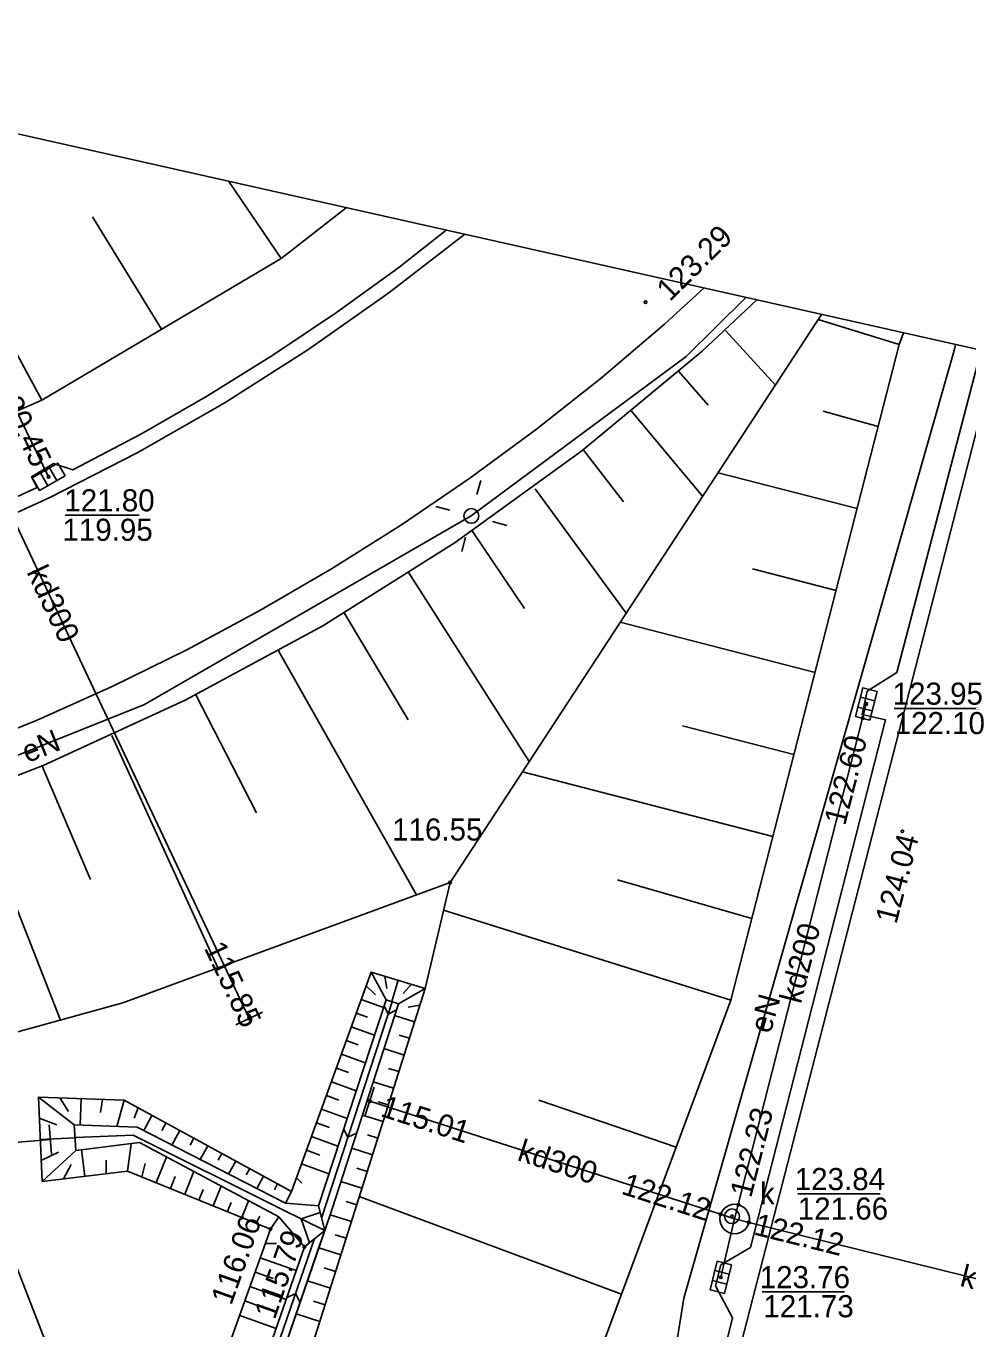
# Model space of a CAD drawing. Extents: x 6424617 to 6425697, y 5665845 to 5667190.
# Drawn here: x 6425429.62 to 6425461.6, y 5666996.15 to 5667040.37 of the extents above; entities that cross this region are included whole.
import ezdxf

# ---------------------------------------------------------------- set-up
doc = ezdxf.new("R2010")
doc.units = 0
for name, color, linetype in [('Warstwa 12', 7, 'Continuous'), ('Warstwa 13', 7, 'Continuous'), ('Warstwa 14', 7, 'Continuous'), ('Warstwa 15', 7, 'Continuous'), ('Warstwa 16', 7, 'Continuous'), ('Warstwa 2', 7, 'Continuous'), ('Warstwa 20', 7, 'Continuous'), ('Warstwa 21', 7, 'Continuous'), ('Warstwa 25', 7, 'Continuous'), ('Warstwa 4', 7, 'Continuous'), ('Warstwa 47', 7, 'Continuous'), ('Warstwa 5', 7, 'Continuous'), ('Warstwa 6', 7, 'Continuous'), ('Warstwa 63', 7, 'Continuous'), ('Warstwa 8', 7, 'Continuous'), ('Warstwa 9', 7, 'Continuous')]:
    doc.layers.add(name, color=color, linetype=linetype)

msp = doc.modelspace()

# ---------------------------------------------------------------- linework, layer by layer
at = {"layer": 'Warstwa 12'}
for points in [[(6425434.76, 5666984.14), (6425434.58, 5666984.61), (6425427.89, 5667001.89), (6425427.65, 5667002.33), (6425427.51, 5667002.81), (6425413.04, 5667037.72)], [(6425425.86, 5667034.37), (6425430.39, 5667025.07)], [(6425437.2, 5667006.68), (6425424.66, 5667033.24)], [(6425454.057, 5667031.16), (6425452.03, 5667029.15), (6425444.74, 5667023.74), (6425433.64, 5667017.34), (6425423.4, 5667013.24), (6425414.37, 5667010.94), (6425408.28, 5667009.82), (6425399.47, 5667009.19), (6425388.9, 5667009.91), (6425381.54, 5667011.18), (6425374.67, 5667013.05), (6425369.27, 5667014.85), (6425364.06, 5667017.3), (6425363.59, 5667017.98), (6425362.65, 5667017.64), (6425356.37, 5667020.95), (6425351.08, 5667024.44)], [(6425431.89, 5666906.96), (6425430.9, 5666907.63), (6425434.54, 5666922.46), (6425436.49, 5666936.39), (6425438.5, 5666937.81), (6425438.62, 5666938.07), (6425450.24, 5666986.45), (6425451.95, 5666997.19), (6425461.13, 5667029.36), (6425461.175, 5667029.564)], [(6425453.68, 5666999.88), (6425458.15, 5667017.36)], [(6425453.68, 5666999.88), (6425453.2, 5667000.04), (6425441.29, 5667003.88)], [(6425427.65, 5667002.33), (6425428.15, 5667002.38), (6425430.45, 5667002.58)], [(6425453.68, 5666999.88), (6425453.21, 5666997.9)], [(6425471.281, 5666995.531), (6425470.8, 5666995.65), (6425454.16, 5666999.76), (6425453.68, 5666999.88)]]:
    msp.add_lwpolyline(points, dxfattribs=at)
at = {"layer": 'Warstwa 14'}
for p, q in [((6425433.461, 5667023.772), (6425430.954, 5667023.772)), ((6425461.961, 5667017.21), (6425459.095, 5667017.21)), ((6425458.619, 5667000.732), (6425455.82, 5667000.732)), ((6425457.405, 5666997.405), (6425454.612, 5666997.405))]:
    msp.add_line(p, q, dxfattribs=at)
for centre in [(6425430.28, 5667025.295), (6425430.39, 5667025.07), (6425458.15, 5667017.36), (6425458.026, 5667016.876), (6425437.2, 5667006.68), (6425441.29, 5667003.88), (6425453.804, 5667000.364), (6425453.2, 5667000.04), (6425453.59, 5666999.97), (6425454.16, 5666999.76), (6425453.21, 5666997.9)]:
    msp.add_circle(centre, 0.045, dxfattribs=at)
at = {"layer": 'Warstwa 16'}
msp.add_circle((6425453.68, 5666999.88), 0.5, dxfattribs=at)
at = {"layer": 'Warstwa 2'}
msp.add_circle((6425444.74, 5667023.74), 0.25, dxfattribs=at)
at = {"layer": 'Warstwa 20'}
for points in [[(6425399.589, 5667018.967), (6425400.677, 5667019.039), (6425401.765, 5667019.127), (6425401.765, 5667019.127), (6425414.98, 5667022.07), (6425422.86, 5667024.48), (6425430.16, 5667027.67), (6425438.29, 5667032.48), (6425440.494, 5667034.201)], [(6425454.431, 5667031.077), (6425452.583, 5667029.336), (6425448.492, 5667025.953), (6425444.19, 5667022.842), (6425439.695, 5667020.016), (6425435.027, 5667017.487), (6425430.205, 5667015.265), (6425425.249, 5667013.361), (6425421.004, 5667012.016), (6425416.691, 5667010.907), (6425412.324, 5667010.035), (6425407.916, 5667009.405), (6425403.48, 5667009.017), (6425399.029, 5667008.872)], [(6425459.415, 5667029.959), (6425459.27, 5667029.56), (6425453.55, 5667007.3), (6425446.123, 5666987.348)], [(6425430.17, 5667001.148), (6425430.041, 5667004.011), (6425432.951, 5667003.909), (6425438.637, 5667000.815), (6425441.342, 5667008.258), (6425443.172, 5667007.705)], [(6425430.17, 5667001.148), (6425433.067, 5667001.506), (6425437.923, 5666999.537), (6425435.131, 5666991.725), (6425437.81, 5666990.75), (6425443.172, 5667007.705)]]:
    msp.add_lwpolyline(points, dxfattribs=at)
at = {"layer": 'Warstwa 21'}
for p, q in [((6425437.653, 5667006.893), (6425436.747, 5667006.467)), ((6425441.443, 5667004.356), (6425441.137, 5667003.404)), ((6425430.493, 5667002.082), (6425430.407, 5667003.078))]:
    msp.add_line(p, q, dxfattribs=at)
for points in [[(6425359.584, 5667018.749), (6425369.708, 5667010.452), (6425371.48, 5667010.531), (6425382.966, 5667006.762), (6425395.305, 5667004.278), (6425404.383, 5667003.424), (6425415.142, 5667003.76), (6425424.988, 5667005.033), (6425432.91, 5667007.21), (6425444.018, 5667011.301), (6425456.633, 5667030.583)], [(6425445.73, 5666975.503), (6425444.579, 5666975.856), (6425443.473, 5666976.33), (6425442.424, 5666976.919), (6425441.443, 5666977.617), (6425440.543, 5666978.417), (6425439.734, 5666979.308), (6425439.025, 5666980.28), (6425438.423, 5666981.322), (6425437.937, 5666982.423), (6425437.571, 5666983.57), (6425437.33, 5666984.749), (6425437.217, 5666985.948), (6425437.232, 5666987.151), (6425437.376, 5666988.346), (6425437.647, 5666989.519), (6425438.041, 5666990.656), (6425437.81, 5666990.75), (6425443.172, 5667007.705), (6425444.018, 5667011.301), (6425456.633, 5667030.583)], [(6425431.319, 5667002.207), (6425431.255, 5667003.079), (6425433.394, 5667002.99), (6425438.429, 5667000.419), (6425439.548, 5667000.328), (6425441.845, 5667007.319), (6425442.263, 5667007.182)], [(6425431.319, 5667002.207), (6425431.508, 5667002.23), (6425433.475, 5667002.469), (6425438.201, 5666999.952), (6425439.073, 5666998.936), (6425436.709, 5666992.137), (6425437.176, 5666991.928), (6425439.763, 5666999.489), (6425440.006, 5667000.19), (6425442.263, 5667007.182)]]:
    msp.add_lwpolyline(points, dxfattribs=at)
at = {"layer": 'Warstwa 25'}
for centre in [(6425450.655, 5667030.998), (6425459.374, 5667013.034), (6425444.018, 5667011.301), (6425437.923, 5666999.537), (6425439.073, 5666998.936)]:
    msp.add_circle(centre, 0.045, dxfattribs=at)
at = {"layer": 'Warstwa 4'}
for p, q in [((6425430.114, 5667025.2), (6425430.363, 5667024.766)), ((6425430.417, 5667025.374), (6425430.666, 5667024.94)), ((6425458.435, 5667017.468), (6425457.951, 5667017.591)), ((6425458.349, 5667017.129), (6425457.865, 5667017.252)), ((6425453.495, 5666998.009), (6425453.01, 5666998.131)), ((6425453.41, 5666997.669), (6425452.925, 5666997.791))]:
    msp.add_line(p, q, dxfattribs=at)
for points in [[(6425429.832, 5667025.038), (6425430.699, 5667025.536), (6425430.948, 5667025.102), (6425430.081, 5667024.604)], [(6425458.516, 5667017.783), (6425458.269, 5667016.814), (6425457.784, 5667016.937), (6425458.031, 5667017.906)], [(6425453.574, 5666998.324), (6425453.331, 5666997.354), (6425452.846, 5666997.476), (6425453.089, 5666998.446)]]:
    msp.add_lwpolyline(points, close=True, dxfattribs=at)
for points in [[(6425444.933, 5667024.465), (6425445.061, 5667024.948)], [(6425444.015, 5667023.933), (6425443.532, 5667024.061)], [(6425445.465, 5667023.547), (6425445.948, 5667023.419)], [(6425444.547, 5667023.015), (6425444.419, 5667022.532)]]:
    msp.add_lwpolyline(points, dxfattribs=at)
msp.add_circle((6425453.59, 5666999.97), 0.25, dxfattribs=at)
at = {"layer": 'Warstwa 47'}
for points in [[(6425440.494, 5667034.201), (6425438.29, 5667032.48), (6425430.16, 5667027.67), (6425422.86, 5667024.48), (6425414.98, 5667022.07)], [(6425459.27, 5667029.56), (6425453.55, 5667007.3), (6425446.123, 5666987.348)]]:
    msp.add_lwpolyline(points, dxfattribs=at)
at = {"layer": 'Warstwa 6'}
for points in [[(6425427.171, 5667023.419), (6425430.005, 5667024.709), (6425429.812, 5667025.072), (6425430.55, 5667025.519), (6425431.216, 5667025.307), (6425433.524, 5667026.52), (6425435.787, 5667027.816), (6425438.002, 5667029.192), (6425440.166, 5667030.646), (6425442.277, 5667032.177), (6425443.891, 5667033.44)], [(6425453.345, 5666995.468), (6425453.604, 5666996.523), (6425453.033, 5666997.614), (6425453.216, 5666998.321), (6425454.217, 5666998.913), (6425458.802, 5667016.816), (6425458.005, 5667017), (6425458.179, 5667017.788), (6425459.191, 5667018.43), (6425462.046, 5667029.369)]]:
    msp.add_lwpolyline(points, dxfattribs=at)
at = {"layer": 'Warstwa 63'}
msp.add_lwpolyline([(6425341.164, 5665895.978), (6425588.9, 5667000.928), (6424898.307, 5667155.763), (6424650.57, 5666050.814)], close=True, dxfattribs=at)
at = {"layer": 'Warstwa 8'}
for p, q in [((6425441.942, 5667031.31), (6425444.517, 5667033.299)), ((6425439.186, 5667029.376), (6425441.942, 5667031.31)), ((6425451.302, 5667030.246), (6425452.645, 5667031.477)), ((6425449.159, 5667028.429), (6425451.302, 5667030.246)), ((6425436.344, 5667027.571), (6425439.186, 5667029.376)), ((6425453.823, 5666995.349), (6425462.575, 5667029.251)), ((6425446.953, 5667026.688), (6425449.159, 5667028.429)), ((6425433.422, 5667025.899), (6425436.344, 5667027.571)), ((6425444.688, 5667025.026), (6425446.953, 5667026.688)), ((6425430.426, 5667024.362), (6425433.422, 5667025.899)), ((6425442.365, 5667023.444), (6425444.688, 5667025.026)), ((6425427.363, 5667022.965), (6425430.426, 5667024.362)), ((6425439.989, 5667021.944), (6425442.365, 5667023.444)), ((6425437.561, 5667020.529), (6425439.989, 5667021.944)), ((6425435.086, 5667019.2), (6425437.561, 5667020.529)), ((6425432.565, 5667017.958), (6425435.086, 5667019.2)), ((6425430.002, 5667016.806), (6425432.565, 5667017.958)), ((6425426.523, 5667015.414), (6425430.002, 5667016.806))]:
    msp.add_line(p, q, dxfattribs=at)
at = {"layer": 'Warstwa 9'}
for p, q in [((6425430.16, 5667027.67), (6425426.161, 5667035.051)), ((6425438.29, 5667032.48), (6425436.505, 5667035.096)), ((6425434.225, 5667030.075), (6425431.877, 5667033.896)), ((6425459.27, 5667029.56), (6425456.521, 5667030.411)), ((6425453.365, 5667030.034), (6425455.063, 5667028.183)), ((6425451.791, 5667028.645), (6425452.786, 5667027.498)), ((6425450.182, 5667027.296), (6425452.594, 5667024.41)), ((6425458.555, 5667026.778), (6425456.687, 5667027.294)), ((6425448.523, 5667026.007), (6425449.91, 5667024.218)), ((6425457.84, 5667023.995), (6425453.118, 5667025.209)), ((6425446.913, 5667024.661), (6425450.001, 5667020.446)), ((6425444.766, 5667023.234), (6425446.548, 5667020.601)), ((6425442.618, 5667021.807), (6425446.707, 5667015.411)), ((6425457.125, 5667021.212), (6425454.291, 5667021.941)), ((6425440.426, 5667020.448), (6425442.594, 5667016.82)), ((6425456.41, 5667018.43), (6425449.795, 5667020.131)), ((6425438.195, 5667019.16), (6425442.876, 5667010.88)), ((6425435.391, 5667017.67), (6425437.442, 5667013.667)), ((6425432.531, 5667016.284), (6425436.136, 5667008.398)), ((6425455.695, 5667015.648), (6425451.914, 5667016.62)), ((6425430.173, 5667015.252), (6425431.812, 5667011.4)), ((6425454.98, 5667012.865), (6425446.473, 5667015.053)), ((6425427.785, 5667014.289), (6425430.796, 5667006.629)), ((6425454.265, 5667010.082), (6425449.7, 5667011.395)), ((6425453.55, 5667007.3), (6425443.797, 5667010.363)), ((6425441.342, 5667008.258), (6425441.845, 5667007.319)), ((6425441.8, 5667008.12), (6425441.87, 5667007.704)), ((6425442.257, 5667007.982), (6425442.038, 5667007.256)), ((6425442.715, 5667007.843), (6425442.432, 5667007.531)), ((6425441.173, 5667007.793), (6425441.487, 5667007.49)), ((6425443.172, 5667007.705), (6425442.263, 5667007.182)), ((6425443.172, 5667007.705), (6425442.263, 5667007.182)), ((6425439.656, 5666999.909), (6425442.054, 5667007.251)), ((6425441.004, 5667007.328), (6425441.758, 5667007.055)), ((6425441.776, 5667007.11), (6425441.917, 5667006.832)), ((6425442.195, 5667006.973), (6425441.917, 5667006.832)), ((6425442.994, 5667007.14), (6425442.596, 5667007.063)), ((6425440.835, 5667006.862), (6425441.219, 5667006.723)), ((6425442.815, 5667006.575), (6425442.136, 5667006.79)), ((6425440.666, 5667006.397), (6425441.449, 5667006.113)), ((6425442.636, 5667006.01), (6425442.295, 5667006.118)), ((6425440.497, 5667005.932), (6425440.896, 5667005.788)), ((6425442.457, 5667005.444), (6425441.772, 5667005.661)), ((6425440.328, 5667005.467), (6425441.14, 5667005.173)), ((6425440.159, 5667005.002), (6425440.572, 5667004.852)), ((6425442.278, 5667004.879), (6425441.934, 5667004.988)), ((6425439.99, 5667004.536), (6425440.83, 5667004.231)), ((6425442.1, 5667004.314), (6425441.408, 5667004.533)), ((6425430.041, 5667004.011), (6425431.255, 5667003.079)), ((6425430.768, 5667003.986), (6425431.064, 5667003.53)), ((6425431.496, 5667003.96), (6425431.465, 5667003.07)), ((6425432.224, 5667003.934), (6425432.155, 5667003.49)), ((6425432.951, 5667003.909), (6425432.708, 5667003.019)), ((6425439.82, 5667004.071), (6425440.248, 5667003.916)), ((6425441.921, 5667003.749), (6425441.574, 5667003.859)), ((6425451.693, 5667002.312), (6425447.03, 5667003.906)), ((6425433.425, 5667003.651), (6425433.294, 5667003.299)), ((6425439.651, 5667003.606), (6425440.521, 5667003.291)), ((6425441.742, 5667003.184), (6425441.044, 5667003.405)), ((6425430.074, 5667003.296), (6425430.672, 5667003.076)), ((6425433.899, 5667003.393), (6425433.618, 5667002.876)), ((6425434.373, 5667003.136), (6425434.235, 5667002.883)), ((6425439.482, 5667003.141), (6425439.924, 5667002.981)), ((6425430.106, 5667002.58), (6425431.288, 5667002.634)), ((6425431.287, 5667002.643), (6425433.256, 5667002.728)), ((6425433.256, 5667002.728), (6425438.322, 5667000.195)), ((6425434.846, 5667002.878), (6425434.578, 5667002.385)), ((6425435.32, 5667002.62), (6425435.19, 5667002.38)), ((6425439.313, 5667002.676), (6425440.212, 5667002.35)), ((6425440.406, 5667002.938), (6425440.551, 5667002.651)), ((6425440.838, 5667002.796), (6425440.551, 5667002.651)), ((6425441.564, 5667002.618), (6425441.213, 5667002.73)), ((6425430.138, 5667001.864), (6425430.721, 5667002.142)), ((6425430.17, 5667001.148), (6425431.319, 5667002.207)), ((6425430.17, 5667001.148), (6425431.319, 5667002.207)), ((6425431.618, 5667001.327), (6425431.508, 5667002.23)), ((6425433.067, 5667001.506), (6425433.189, 5667002.434)), ((6425435.794, 5667002.362), (6425435.54, 5667001.894)), ((6425436.268, 5667002.104), (6425436.144, 5667001.876)), ((6425439.144, 5667002.21), (6425439.601, 5667002.045)), ((6425441.385, 5667002.053), (6425440.68, 5667002.277)), ((6425430.894, 5667001.238), (6425431.154, 5667001.728)), ((6425432.342, 5667001.416), (6425432.346, 5667001.874)), ((6425433.552, 5667001.309), (6425433.671, 5667001.758)), ((6425434.038, 5667001.112), (6425434.391, 5667001.981)), ((6425436.742, 5667001.846), (6425436.501, 5667001.403)), ((6425438.975, 5667001.745), (6425439.903, 5667001.409)), ((6425434.523, 5667000.915), (6425434.69, 5667001.324)), ((6425435.009, 5667000.718), (6425435.321, 5667001.486)), ((6425437.216, 5667001.589), (6425437.098, 5667001.373)), ((6425437.689, 5667001.331), (6425437.462, 5667000.913)), ((6425438.806, 5667001.28), (6425438.986, 5667001.097)), ((6425441.206, 5667001.488), (6425440.852, 5667001.6)), ((6425435.495, 5667000.522), (6425435.64, 5667000.88)), ((6425435.981, 5667000.325), (6425436.251, 5667000.99)), ((6425438.163, 5667001.073), (6425438.054, 5667000.87)), ((6425438.637, 5667000.815), (6425438.429, 5667000.419)), ((6425441.027, 5667000.923), (6425440.315, 5667001.149)), ((6425436.466, 5667000.128), (6425436.591, 5667000.435)), ((6425436.952, 5666999.931), (6425437.181, 5667000.495)), ((6425440.848, 5667000.358), (6425440.49, 5667000.472)), ((6425449.836, 5666997.324), (6425440.937, 5667000.638)), ((6425437.438, 5666999.734), (6425437.564, 5666999.979)), ((6425437.923, 5666999.537), (6425438.201, 5666999.952)), ((6425438.322, 5667000.195), (6425439.763, 5666999.489)), ((6425439.607, 5667000.097), (6425438.969, 5666999.878)), ((6425439.244, 5666999.073), (6425438.969, 5666999.878)), ((6425440.67, 5666999.793), (6425439.948, 5667000.022)), ((6425436.943, 5666992.033), (6425439.418, 5666999.213)), ((6425437.749, 5666999.049), (6425438.123, 5666999.044)), ((6425440.491, 5666999.228), (6425440.122, 5666999.344)), ((6425437.574, 5666998.561), (6425438.792, 5666998.127)), ((6425440.312, 5666998.662), (6425439.559, 5666998.901)), ((6425440.134, 5666998.097), (6425439.75, 5666998.218)), ((6425437.399, 5666998.072), (6425438.01, 5666997.855)), ((6425439.955, 5666997.532), (6425439.175, 5666997.779)), ((6425437.225, 5666997.584), (6425438.451, 5666997.147)), ((6425438.471, 5666997.204), (6425438.777, 5666997.353)), ((6425438.926, 5666997.048), (6425438.777, 5666997.353)), ((6425437.05, 5666997.096), (6425437.666, 5666996.876)), ((6425439.776, 5666996.967), (6425439.38, 5666997.092)), ((6425436.876, 5666996.608), (6425438.11, 5666996.166)), ((6425439.597, 5666996.402), (6425438.792, 5666996.657))]:
    msp.add_line(p, q, dxfattribs=at)
for points in [[(6425440.494, 5667034.201), (6425438.29, 5667032.48), (6425430.16, 5667027.67), (6425422.86, 5667024.48), (6425414.98, 5667022.07), (6425401.765, 5667019.127), (6425401.765, 5667019.127), (6425400.677, 5667019.039), (6425399.589, 5667018.967)], [(6425454.431, 5667031.077), (6425452.583, 5667029.336), (6425448.492, 5667025.953), (6425444.19, 5667022.842), (6425439.695, 5667020.016), (6425435.027, 5667017.487), (6425430.205, 5667015.265), (6425425.249, 5667013.361), (6425421.004, 5667012.016), (6425416.691, 5667010.907), (6425412.324, 5667010.035), (6425407.916, 5667009.405), (6425403.48, 5667009.017), (6425399.029, 5667008.872)], [(6425395.305, 5667004.278), (6425404.383, 5667003.424), (6425415.142, 5667003.76), (6425424.988, 5667005.033), (6425432.91, 5667007.21), (6425444.018, 5667011.301), (6425456.633, 5667030.583)], [(6425437.81, 5666990.75), (6425443.172, 5667007.705), (6425444.018, 5667011.301), (6425456.633, 5667030.583)], [(6425459.415, 5667029.959), (6425459.27, 5667029.56), (6425453.55, 5667007.3), (6425446.123, 5666987.348)]]:
    msp.add_lwpolyline(points, dxfattribs=at)
for points in [[(6425430.17, 5667001.148), (6425431.319, 5667002.207), (6425431.255, 5667003.079), (6425433.394, 5667002.99), (6425438.429, 5667000.419), (6425439.548, 5667000.328), (6425441.845, 5667007.319), (6425442.263, 5667007.182), (6425443.172, 5667007.705), (6425441.342, 5667008.258), (6425438.637, 5667000.815), (6425432.951, 5667003.909), (6425430.041, 5667004.011)], [(6425430.17, 5667001.148), (6425431.319, 5667002.207), (6425431.508, 5667002.23), (6425433.475, 5667002.469), (6425438.201, 5666999.952), (6425439.073, 5666998.936), (6425436.709, 5666992.137), (6425437.176, 5666991.928), (6425439.763, 5666999.489), (6425440.006, 5667000.19), (6425442.263, 5667007.182), (6425443.172, 5667007.705), (6425437.81, 5666990.75), (6425435.131, 5666991.725), (6425437.923, 5666999.537), (6425433.067, 5667001.506)], [(6425441.845, 5667007.319), (6425442.263, 5667007.182), (6425440.006, 5667000.19), (6425439.763, 5666999.489), (6425439.548, 5667000.328)], [(6425431.255, 5667003.079), (6425433.394, 5667002.99), (6425438.429, 5667000.419), (6425439.548, 5667000.328), (6425439.763, 5666999.489), (6425439.073, 5666998.936), (6425438.201, 5666999.952), (6425433.475, 5667002.469), (6425431.319, 5667002.207)], [(6425439.073, 5666998.936), (6425439.763, 5666999.489), (6425439.52, 5666998.788), (6425437.176, 5666991.928), (6425436.709, 5666992.137)]]:
    msp.add_lwpolyline(points, close=True, dxfattribs=at)

# ---------------------------------------------------------------- texts
at = {"layer": 'Warstwa 13'}
for s, rotation, p in [('kd300', 295.2738, (6425429.629, 5667021.837)), ('eN', 21.8182, (6425429.667, 5667015.345)), ('kd200', 75.6533, (6425455.927, 5667007.155)), ('eN', 74.072, (6425454.894, 5667006.139)), ('kd300', 342.1303, (6425446.265, 5667001.882)), ('kd300', 346.1238, (6425461.298, 5666997.611))]:
    msp.add_text(s, height=0.75, rotation=rotation, dxfattribs=at).set_placement(p)
at = {"layer": 'Warstwa 14'}
for s, rotation, p in [('120.45', 295.9728, (6425428.502, 5667028.087)), ('122.60', 75.6533, (6425457.431, 5667013.205)), ('115.85', 295.2738, (6425435.654, 5667009.078)), ('115.01', 342.1303, (6425441.62, 5667003.379)), ('122.23', 75.6533, (6425454.238, 5667000.569)), ('122.12', 342.1303, (6425449.799, 5667000.742)), ('122.12', 346.1238, (6425454.296, 5666999.355))]:
    msp.add_text(s, height=0.75, rotation=rotation, dxfattribs=at).set_placement(p)
for s, p in [('119.95', (6425430.858, 5667022.896)), ('122.10', (6425459.112, 5667016.334)), ('121.66', (6425455.824, 5666999.857)), ('121.73', (6425454.656, 5666996.543))]:
    msp.add_text(s, height=0.75, dxfattribs=at).set_placement(p)
at = {"layer": 'Warstwa 15'}
for s, p in [('121.80', (6425430.922, 5667023.896)), ('123.95', (6425459.043, 5667017.334)), ('123.84', (6425455.72, 5667000.857)), ('123.76', (6425454.53, 5666997.529))]:
    msp.add_text(s, height=0.75, dxfattribs=at).set_placement(p)
at = {"layer": 'Warstwa 25'}
for s, rotation, p in [('123.29', 44.7537, (6425451.482, 5667030.991)), ('124.04', 75.5216, (6425459.17, 5667009.858)), ('116.06', 70.3306, (6425436.59, 5666996.921)), ('115.79', 70.829, (6425438.065, 5666996.434))]:
    msp.add_text(s, height=0.75, rotation=rotation, dxfattribs=at).set_placement(p)
msp.add_text('116.55', height=0.75, dxfattribs=at).set_placement((6425442.051, 5667012.723))
at = {"layer": 'Warstwa 5'}
msp.add_text('k', height=0.75, dxfattribs=at).set_placement((6425454.541, 5667000.371))

doc.saveas('drawing.dxf')
